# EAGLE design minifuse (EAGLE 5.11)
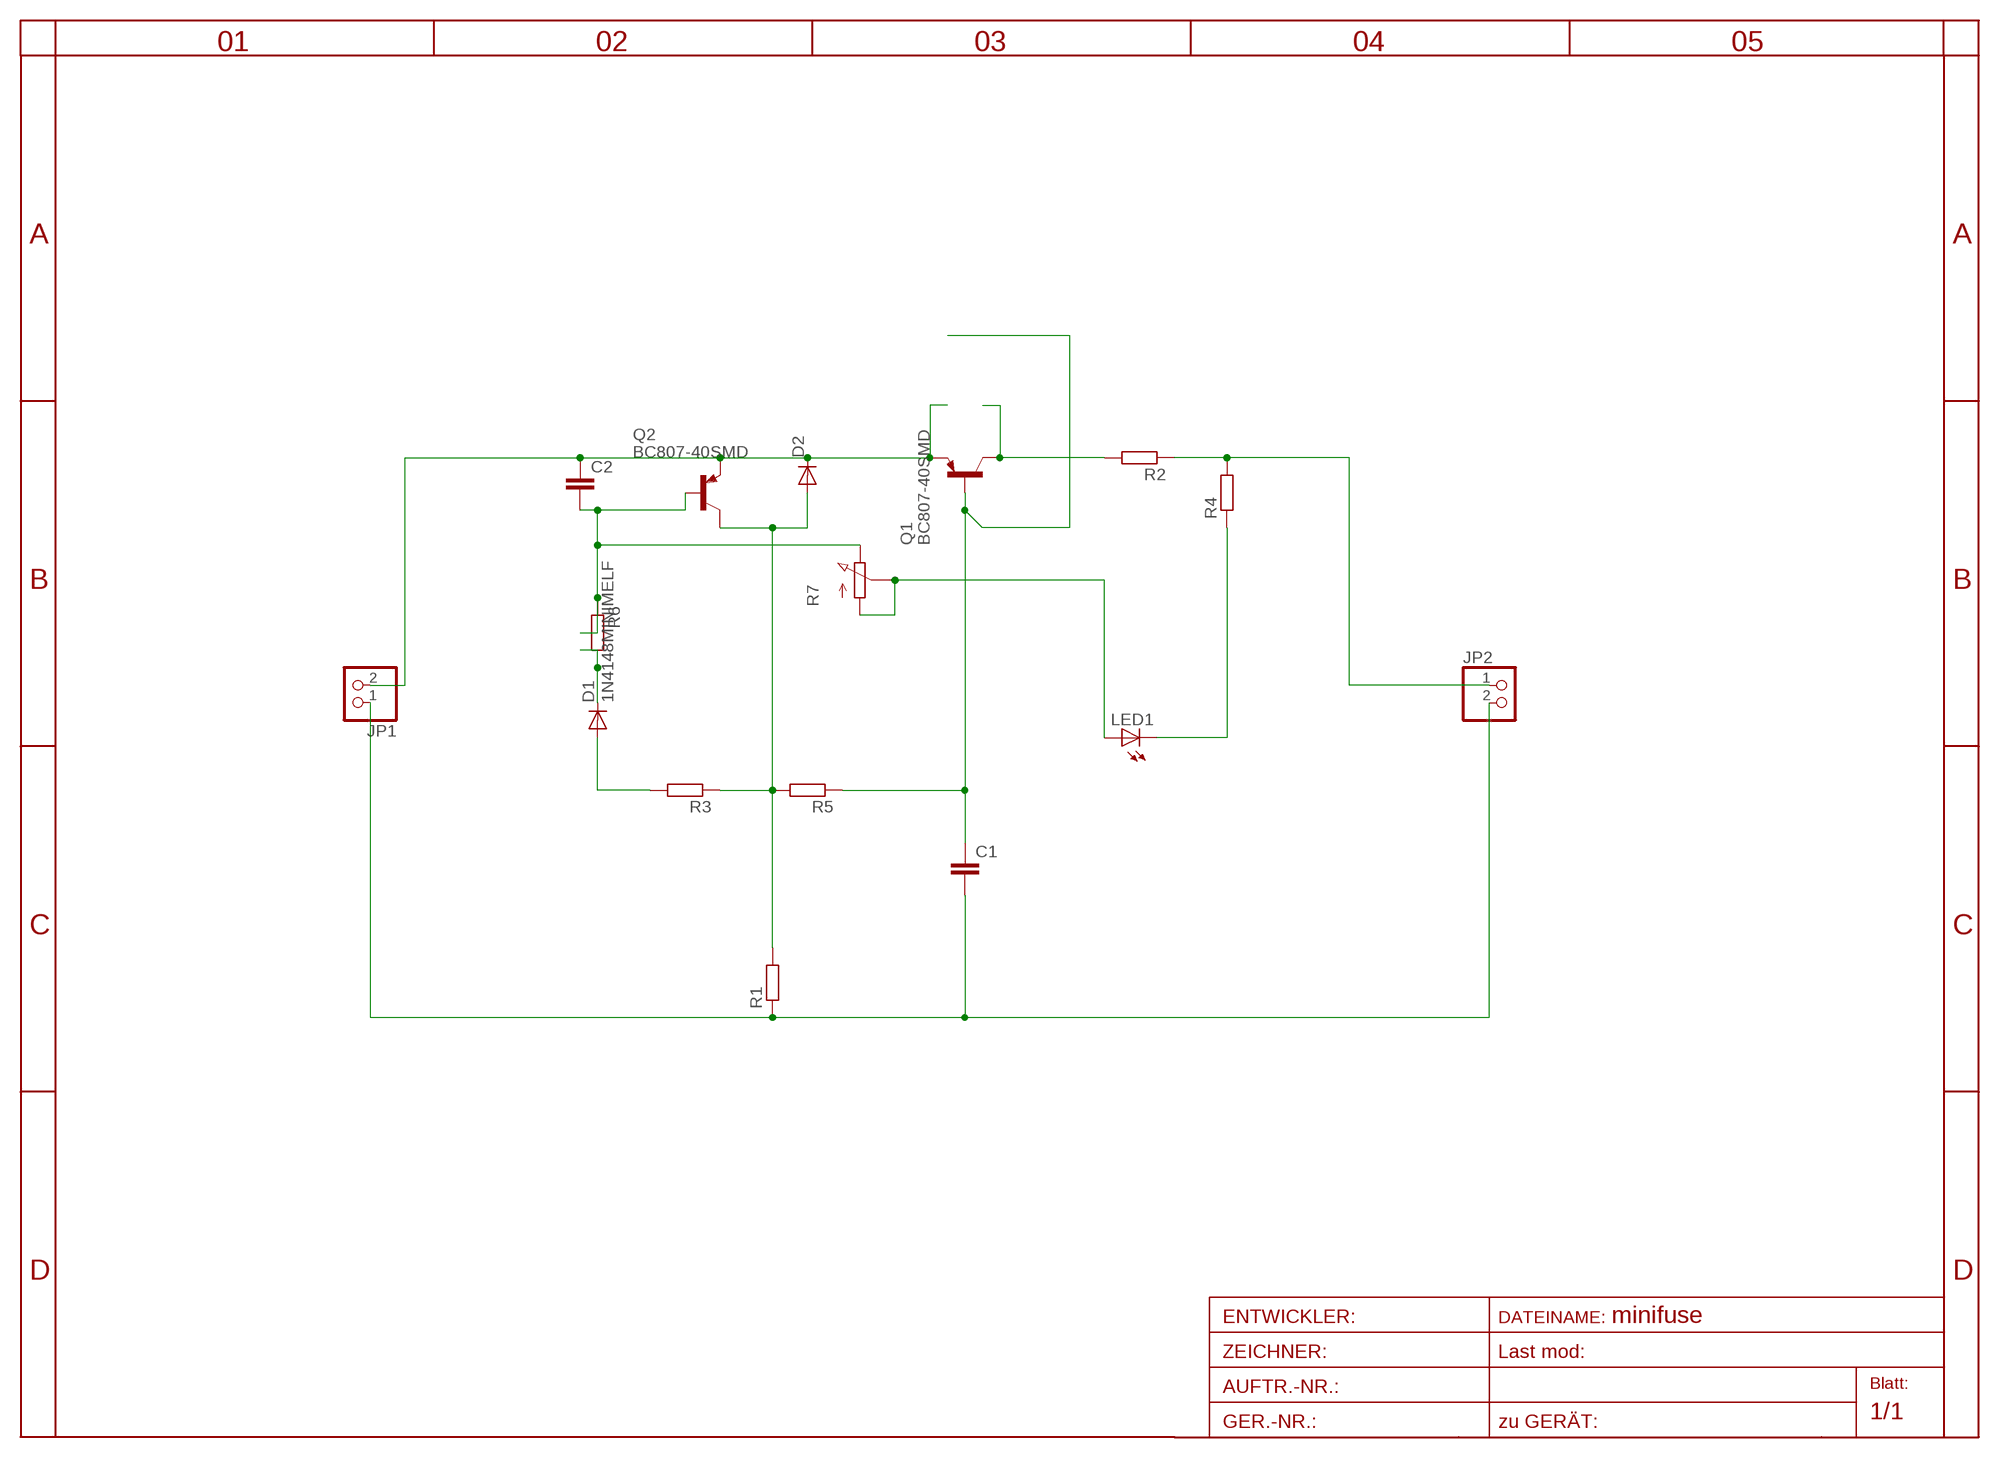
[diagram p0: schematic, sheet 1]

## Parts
C1  C-EUC0805  [C0805]
C2  C-EUC0805  [C0805]
D1  1N4148MINIMELF  [MINIMELF]
D2  DIODE-MINIMELF  [MINIMELF]
JP1  PINHD-1X2  [1X02]
JP2  PINHD-1X2  [1X02]
LED1  LEDSMT1206  [1206]
Q1  BC807-40SMD  [SOT23-BEC]
Q2  BC807-40SMD  [SOT23-BEC]
R1  R-EU_R0805  [R0805]
R2  R-EU_0204/7  [0204/7]
R3  R-EU_R0805  [R0805]
R4  R-EU_R0805  [R0805]
R5  R-EU_R0805  [R0805]
R6  R-EU_R0402  [R0402]
R7  PC25  [PC25]

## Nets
N$2: C2.1 D2.C JP1.2 Q1.E Q2.E
N$3: LED1.A R7.A R7.S
N$4: D2.A Q2.C R1.2 R3.1 R5.2
N$5: D1.A R3.2
N$6: D1.C R6.2
N$7: C1.1 Q1.B R5.1
N$8: JP2.1 R2.1 R4.2
N$9: Q1.C R2.2
N$11: LED1.C R4.1
N$12: C2.2 Q2.B R6.1 R7.E
V-: C1.2 JP1.1 JP2.2 R1.1

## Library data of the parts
C1 C2 = rcl-2:C-EU: CAPACITOR, European symbol
D1 = diode-1:1N4148: DIODE
D2 = diode-1:DIODE-: DIODE
JP1 JP2 = pinhead:PINHD-1X2: PIN HEADER
LED1 = led:LED: LED
Q1 Q2 = transistor-pnp:BC807*: PNP Transistror
R1-R6 = rcl-2:R-EU_: RESISTOR, European symbol
R7 = pot-vitrohm:PC25: VITROHM POTENTIOMETER; MF: CLAROSTAT; MPN: 308NPC25KS; OC_FARNELL: 1440998; OC_NEWARK: 03F7518

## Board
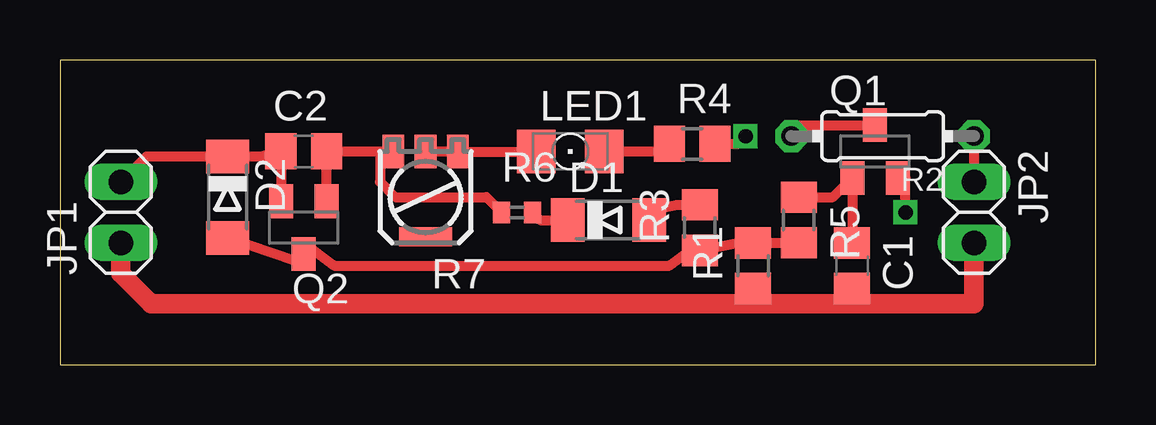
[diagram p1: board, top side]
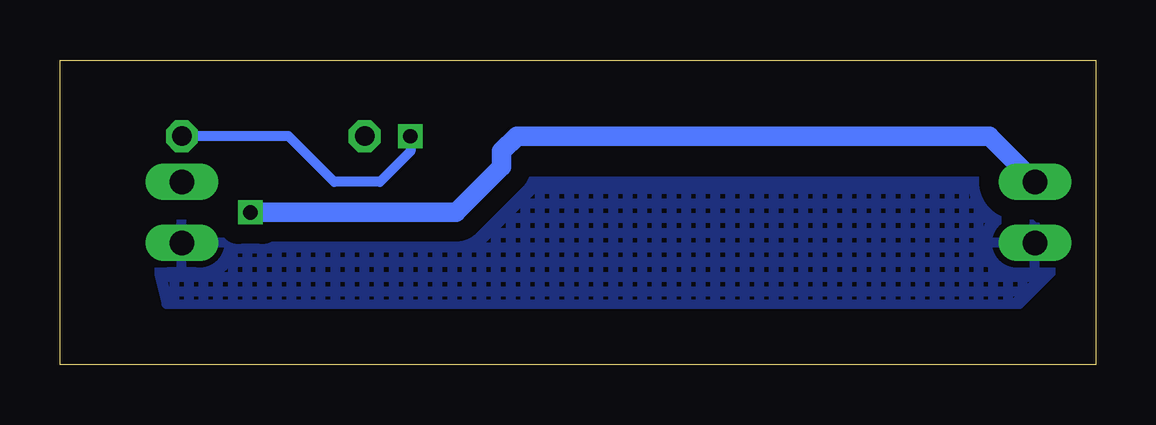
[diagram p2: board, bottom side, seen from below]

Size 43.18 x 12.7 mm. Coordinates in mm from the lower left corner, seen from the top.
Outline: 0,0 43.18,0 43.18,12.7 0,12.7 0,0
Copper layers (1*16): Top 0.035mm / dielectric 1.5mm / Bottom 0.035mm
Design rules "default": minimum track width 10mil, minimum drill 24mil, track to track 8mil, track to pad 8mil, pad to pad 8mil, via to via 8mil, smd to smd 8mil, copper to edge 40mil, drill to drill 8mil, minimum pad ring 10mil, minimum via ring 8mil, stop-mask expansion 4mil, vias tented up to drill 0mil, thermal gap 10mil

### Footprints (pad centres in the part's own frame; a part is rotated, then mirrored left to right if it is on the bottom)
C0805 = smd 1.3 x 1.5: 1 -0.95,0; 2 0.95,0
MINIMELF = smd 1.4 x 1.8: A 1.7,0; C -1.7,0
1X02 = drill 1.016 long: 1 -1.27,0; 2 1.27,0
1206 = smd 1.6 x 1.803: A -1.422,0; C 1.422,0
SOT23-BEC = smd 1 x 1.4: B -0.95,-1.1; C 0,1.1; E 0.95,-1.1
R0805 = smd 1.3 x 1.5: 1 -0.95,0; 2 0.95,0
0204/7 = drill 0.813 octagon: 1 -3.81,0; 2 3.81,0
R0402 = smd 0.7 x 0.9: 1 -0.65,0; 2 0.65,0
PC25 = smd 2.2 x 0.8: 4 0,1.65 | smd 0.9 x 1.4: A -1.35,-1.9; E 1.35,-1.9; S 0,-1.9

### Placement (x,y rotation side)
C1  33.02,4.13 270 top
C2  10.16,8.89 0 top
D1  22.86,6.03 0 top
D2  6.99,6.99 270 top
JP1  2.54,6.35 90 top
JP2  38.1,6.35 270 top
LED1  21.27,8.89 0 top
Q1  33.97,8.89 0 top
Q2  10.16,5.71 180 top
R1  28.89,4.13 90 top
R2  34.29,9.53 180 top
R3  26.67,5.71 90 top
R4  26.35,9.21 0 top
R5  30.8,6.03 270 top
R6  19.05,6.35 0 top
R7  15.24,6.99 180 top

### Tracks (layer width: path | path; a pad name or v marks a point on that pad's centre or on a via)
N$2  (via drill 0.6)
  Top 0.406: Q2.E C2.1 8.37,8.69 D2.C 3.6,8.69 JP1.2 | Q1.E 35.24,7.79 v35.24,6.35
  Bottom 0.813: v35.24,6.35 26.67,6.35 24.77,8.26 24.77,8.89 24.13,9.53 4.45,9.53 JP1.2
N$3
  Top 0.406: R7.S R7.A LED1.A
N$4
  Top 0.406: D2.A 9.81,4.33 Q2.C 10.16,5.08 11.43,4.13 25.4,4.13 26.67,5.08 R3.1 28.25,5.08 R1.2 29.85,5.08 R5.2
N$5
  Top 0.406: R3.2 25.71,6.67 24.13,6.35 D1.A
N$6
  Top 0.406: D1.C 20.02,6.03 R6.2
N$7
  Top 0.406: R5.1 32.22,6.98 Q1.B C1.1
N$8  (via drill 0.6)
  Top 0.406: R2.1 JP2.1 | R4.2 28.26,9.21 v28.57,9.53
  Bottom 0.406: v28.57,9.53 28.57,8.89 29.84,7.62 31.75,7.62 33.66,9.53 R2.1
N$9
  Top 0.406: Q1.C 30.65,9.99 R2.2
N$11
  Top 0.406: LED1.C 25.09,8.89 R4.1
N$12
  Top 0.406: Q2.B C2.2 13.34,8.89 | 13.34,8.89 R7.E | R6.1 18.4,6.37 17.78,6.99 13.97,6.99 13.34,7.62 13.34,8.89
V-
  Top 0.406: 29.21,2.54 R1.1 | 33.02,2.54 C1.2
  Top 0.813: JP1.1 2.54,3.81 3.81,2.54 29.21,2.54 33.02,2.54 38.1,2.54 JP2.2
  pour Bottom (isolate 0.813, hatched): 1.27,5.71 2.54,5.71 4.45,7.62 24.13,7.62 25.4,6.35 38.73,6.35 39.37,5.08 38.73,2.54 3.17,2.54 1.27,4.45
